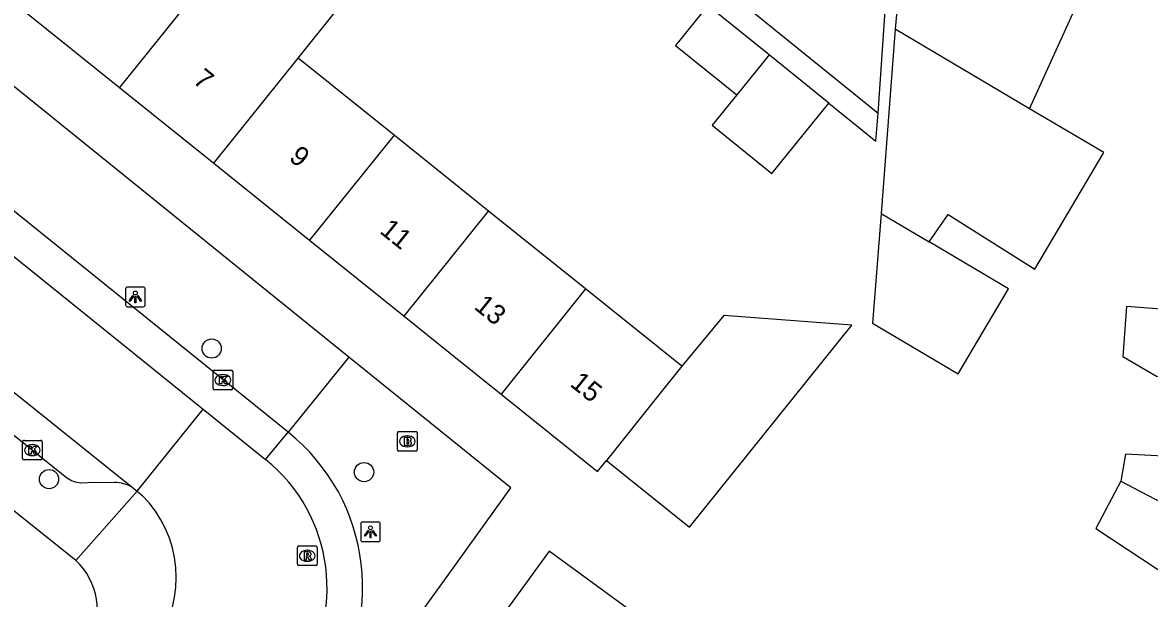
# Model space of a CAD drawing. Extents: x 160107 to 160928, y 382056 to 382918.
# Drawn here: x 160478.2 to 160535.6, y 382552.9 to 382582.2 of the extents above; entities that cross this region are included whole.
import ezdxf

# ---------------------------------------------------------------- set-up
doc = ezdxf.new("R2010")
doc.units = 0
for name, color, linetype in [('IMGEO_Boom', 7, 'Continuous'), ('IMGEO_Brandkraan', 7, 'Continuous'), ('IMGEO_Kolk', 7, 'Continuous'), ('IMGEO_Lichtpunt', 7, 'Continuous'), ('IMGEO_Pand', 7, 'Continuous'), ('IMGEO_Pand_nummerreeks', 7, 'Continuous'), ('IMGEO_Parkeervlak_open', 7, 'Continuous'), ('IMGEO_Rijbaan_lokaal_open', 7, 'Continuous'), ('IMGEO_Rioolput', 7, 'Continuous'), ('IMGEO_Voetpad_open', 7, 'Continuous')]:
    doc.layers.add(name, color=color, linetype=linetype)

msp = doc.modelspace()

# ---------------------------------------------------------------- linework, layer by layer
at = {"layer": 'IMGEO_Boom'}
for centre in [(160487.844, 382565.584), (160479.567, 382558.934), (160495.604, 382559.293)]:
    msp.add_circle(centre, 0.489, dxfattribs=at)
at = {"layer": 'IMGEO_Brandkraan'}
for p, q in [((160497.304, 382560.433), (160497.304, 382561.285)), ((160497.379, 382561.359), (160498.231, 382561.359)), ((160497.792, 382561.139), (160497.817, 382561.139)), ((160498.305, 382561.285), (160498.305, 382560.433)), ((160497.815, 382560.579), (160497.79, 382560.579)), ((160498.231, 382560.359), (160497.379, 382560.359))]:
    msp.add_line(p, q, dxfattribs=at)
for points in [[(160497.304, 382560.433), (160497.304, 382561.285)], [(160497.379, 382561.359), (160498.231, 382561.359)], [(160498.305, 382561.285), (160498.305, 382560.433)], [(160497.652, 382561.059), (160497.652, 382560.659), (160497.865, 382560.659)], [(160497.883, 382561.059), (160497.652, 382561.059)], [(160497.831, 382560.978), (160497.777, 382560.978), (160497.777, 382560.902)], [(160497.777, 382560.902), (160497.83, 382560.902)], [(160497.839, 382560.826), (160497.777, 382560.826), (160497.777, 382560.745)], [(160497.777, 382560.745), (160497.839, 382560.745)], [(160498.231, 382560.359), (160497.379, 382560.359)]]:
    msp.add_lwpolyline(points, dxfattribs=at)
for centre, radius, start, end in [((160497.381, 382561.283), 0.0765, 91.55205, 178.44795), ((160497.381, 382561.283), 0.0765, 91.55205, 178.44795), ((160498.229, 382561.283), 0.0765, 1.55205, 88.44795), ((160498.229, 382561.283), 0.0765, 1.55205, 88.44795), ((160497.832, 382560.94), 0.0379, 267.82845, 90.93552), ((160497.84, 382560.785), 0.0404, 269.87594, 90.50774), ((160497.871, 382560.91), 0.251, 268.66757, 293.53466), ((160497.887, 382560.914), 0.145, 59.4692, 91.53667), ((160497.912, 382560.961), 0.0922, 285.51372, 58.15012), ((160497.917, 382560.769), 0.105, 301.31148, 78.98903), ((160497.381, 382560.435), 0.0765, 181.55205, 268.44795), ((160497.381, 382560.435), 0.0765, 181.55205, 268.44795), ((160498.229, 382560.435), 0.0765, 271.55205, 358.44795), ((160498.229, 382560.435), 0.0765, 271.55205, 358.44795)]:
    msp.add_arc(centre, radius, start, end, dxfattribs=at)
for centre, major_axis, ratio, start_param, end_param in [((160497.791, 382560.859), (-0.387, 0.002), 0.722429, 4.712389, 7.853982), ((160497.816, 382560.859), (-0.39, 0.002), 0.717154, 1.570796, 4.712389)]:
    msp.add_ellipse(centre, major_axis=major_axis, ratio=ratio, start_param=start_param, end_param=end_param, dxfattribs=at)
at = {"layer": 'IMGEO_Kolk'}
for p, q in [((160487.915, 382563.554), (160487.915, 382564.406)), ((160487.99, 382564.48), (160488.842, 382564.48)), ((160488.403, 382564.26), (160488.428, 382564.26)), ((160488.916, 382564.406), (160488.916, 382563.554)), ((160488.842, 382563.48), (160487.99, 382563.48)), ((160488.426, 382563.7), (160488.401, 382563.7)), ((160478.217, 382559.984), (160478.217, 382560.836)), ((160478.292, 382560.91), (160479.144, 382560.91)), ((160478.705, 382560.69), (160478.73, 382560.69)), ((160479.218, 382560.836), (160479.218, 382559.984)), ((160478.728, 382560.13), (160478.703, 382560.13)), ((160479.144, 382559.91), (160478.292, 382559.91))]:
    msp.add_line(p, q, dxfattribs=at)
for points in [[(160487.915, 382563.554), (160487.915, 382564.406)], [(160487.99, 382564.48), (160488.842, 382564.48)], [(160488.236, 382564.18), (160488.359, 382564.18), (160488.359, 382564.029), (160488.489, 382564.18), (160488.653, 382564.18), (160488.507, 382564.029), (160488.66, 382563.78), (160488.508, 382563.78), (160488.423, 382563.944), (160488.359, 382563.877), (160488.359, 382563.78), (160488.236, 382563.78), (160488.236, 382564.18)], [(160488.916, 382564.406), (160488.916, 382563.554)], [(160488.842, 382563.48), (160487.99, 382563.48)], [(160478.217, 382559.984), (160478.217, 382560.836)], [(160478.292, 382560.91), (160479.144, 382560.91)], [(160478.538, 382560.61), (160478.661, 382560.61), (160478.661, 382560.459), (160478.791, 382560.61), (160478.955, 382560.61), (160478.809, 382560.459), (160478.962, 382560.21), (160478.81, 382560.21), (160478.725, 382560.374), (160478.661, 382560.307), (160478.661, 382560.21), (160478.538, 382560.21), (160478.538, 382560.61)], [(160479.218, 382560.836), (160479.218, 382559.984)], [(160479.144, 382559.91), (160478.292, 382559.91)]]:
    msp.add_lwpolyline(points, dxfattribs=at)
for centre, start, end in [((160487.992, 382564.404), 91.55205, 178.44795), ((160487.992, 382564.404), 91.55205, 178.44795), ((160488.84, 382564.404), 1.55205, 88.44795), ((160488.84, 382564.404), 1.55205, 88.44795), ((160487.992, 382563.556), 181.55205, 268.44795), ((160487.992, 382563.556), 181.55205, 268.44795), ((160488.84, 382563.556), 271.55205, 358.44795), ((160488.84, 382563.556), 271.55205, 358.44795), ((160478.294, 382560.834), 91.55205, 178.44795), ((160478.294, 382560.834), 91.55205, 178.44795), ((160479.142, 382560.834), 1.55205, 88.44795), ((160479.142, 382560.834), 1.55205, 88.44795), ((160478.294, 382559.986), 181.55205, 268.44795), ((160478.294, 382559.986), 181.55205, 268.44795), ((160479.142, 382559.986), 271.55205, 358.44795), ((160479.142, 382559.986), 271.55205, 358.44795)]:
    msp.add_arc(centre, 0.0765, start, end, dxfattribs=at)
for centre, major_axis, ratio, start_param, end_param in [((160488.402, 382563.98), (-0.387, 0.002), 0.722429, 4.712389, 7.853982), ((160488.427, 382563.98), (-0.39, 0.002), 0.717154, 1.570796, 4.712389), ((160478.704, 382560.41), (-0.387, 0.002), 0.722429, 4.712389, 7.853982), ((160478.729, 382560.41), (-0.39, 0.002), 0.717154, 1.570796, 4.712389)]:
    msp.add_ellipse(centre, major_axis=major_axis, ratio=ratio, start_param=start_param, end_param=end_param, dxfattribs=at)
at = {"layer": 'IMGEO_Lichtpunt'}
for p, q in [((160483.463, 382568.612), (160483.463, 382567.805)), ((160483.463, 382568.612), (160483.463, 382567.805)), ((160484.365, 382568.707), (160483.557, 382568.707)), ((160484.365, 382568.707), (160483.557, 382568.707)), ((160484.459, 382567.805), (160484.459, 382568.612)), ((160484.459, 382567.805), (160484.459, 382568.612)), ((160483.557, 382567.711), (160484.365, 382567.711)), ((160483.557, 382567.711), (160484.365, 382567.711)), ((160495.431, 382556.655), (160495.431, 382555.848)), ((160495.431, 382556.655), (160495.431, 382555.848)), ((160496.333, 382556.75), (160495.525, 382556.75)), ((160496.333, 382556.75), (160495.525, 382556.75)), ((160496.427, 382555.848), (160496.427, 382556.655)), ((160496.427, 382555.848), (160496.427, 382556.655)), ((160495.525, 382555.754), (160496.333, 382555.754)), ((160495.525, 382555.754), (160496.333, 382555.754))]:
    msp.add_line(p, q, dxfattribs=at)
for points in [[(160483.837, 382568.276), (160483.876, 382568.248), (160483.688, 382567.986), (160483.65, 382568.013), (160483.837, 382568.276)], [(160483.939, 382568.228), (160483.986, 382568.228), (160483.986, 382567.906), (160483.939, 382567.906), (160483.939, 382568.228)], [(160484.049, 382568.248), (160484.087, 382568.275), (160484.274, 382568.013), (160484.235, 382567.985), (160484.049, 382568.248)], [(160495.805, 382556.319), (160495.844, 382556.291), (160495.656, 382556.029), (160495.618, 382556.056), (160495.805, 382556.319)], [(160495.907, 382556.271), (160495.954, 382556.271), (160495.954, 382555.949), (160495.907, 382555.949), (160495.907, 382556.271)], [(160496.017, 382556.291), (160496.055, 382556.318), (160496.242, 382556.056), (160496.203, 382556.028), (160496.017, 382556.291)]]:
    msp.add_lwpolyline(points, dxfattribs=at)
for centre in [(160483.962, 382568.41), (160495.93, 382556.453)]:
    msp.add_circle(centre, 0.0994, dxfattribs=at)
for centre, start, end in [((160483.557, 382568.612), 90, 180), ((160483.557, 382568.612), 90, 180), ((160484.365, 382568.612), 0, 90), ((160484.365, 382568.612), 0, 90), ((160483.557, 382567.805), 180, 270), ((160483.557, 382567.805), 180, 270), ((160484.365, 382567.805), 270, 0), ((160484.365, 382567.805), 270, 360), ((160495.525, 382556.655), 90, 180), ((160495.525, 382556.655), 90, 180), ((160496.333, 382556.655), 0, 90), ((160496.333, 382556.655), 0, 90), ((160495.525, 382555.848), 180, 270), ((160495.525, 382555.848), 180, 270), ((160496.333, 382555.848), 270, 0), ((160496.333, 382555.848), 270, 360)]:
    msp.add_arc(centre, 0.0946, start, end, dxfattribs=at)
at = {"layer": 'IMGEO_Pand'}
for points in [[(160523.021, 382587.864), (160522.708, 382582.592), (160522.649, 382581.836)], [(160492.247, 382580.362), (160494.172, 382582.757), (160489.365, 382586.621), (160487.442, 382584.218)], [(160529.486, 382577.794), (160532.105, 382583.595), (160529.137, 382584.927), (160529.152, 382585.097)], [(160487.442, 382584.218), (160483.149, 382578.878)], [(160513.108, 382583.049), (160511.462, 382581.014), (160514.58, 382578.492)], [(160516.219, 382580.531), (160513.108, 382583.049)], [(160478.25, 382582.816), (160483.149, 382578.878)], [(160522.649, 382581.836), (160521.921, 382572.453)], [(160529.486, 382577.794), (160522.649, 382581.836)], [(160487.952, 382575.018), (160492.247, 382580.362)], [(160497.131, 382576.442), (160492.247, 382580.362)], [(160516.219, 382580.531), (160514.58, 382578.492)], [(160519.258, 382578.07), (160516.219, 382580.531)], [(160483.149, 382578.878), (160487.952, 382575.018)], [(160514.58, 382578.492), (160513.332, 382576.949), (160516.366, 382574.495), (160519.258, 382578.07)], [(160524.366, 382571.009), (160525.337, 382572.407), (160529.753, 382569.63), (160533.26, 382575.563), (160529.486, 382577.794)], [(160497.131, 382576.442), (160492.833, 382571.095)], [(160501.942, 382572.581), (160500, 382574.14), (160497.131, 382576.442)], [(160487.952, 382575.018), (160492.833, 382571.095)], [(160497.641, 382567.23), (160500, 382570.165), (160501.942, 382572.581)], [(160506.884, 382568.616), (160501.942, 382572.581)], [(160521.921, 382572.453), (160521.488, 382566.867), (160525.848, 382564.292), (160528.406, 382568.623), (160524.366, 382571.009)], [(160521.921, 382572.453), (160524.366, 382571.009)], [(160492.833, 382571.095), (160497.641, 382567.23)], [(160552.564, 382569.329), (160547.58, 382569.718), (160544.296, 382569.974), (160541.327, 382570.206), (160541.092, 382567.202), (160538.823, 382567.379), (160534.423, 382567.722), (160534.226, 382565.184), (160535.938, 382564.173), (160538.538, 382563.615), (160543.727, 382563.248), (160547.056, 382562.989), (160552.04, 382562.601)], [(160506.884, 382568.616), (160502.579, 382563.261)], [(160511.788, 382564.68), (160506.884, 382568.616)], [(160497.641, 382567.23), (160500, 382565.334), (160502.579, 382563.261)], [(160507.938, 382559.891), (160512.167, 382556.49), (160520.438, 382566.776), (160513.923, 382567.267), (160511.788, 382564.68)], [(160511.788, 382564.68), (160510.614, 382563.219), (160507.938, 382559.891)], [(160502.579, 382563.261), (160507.48, 382559.322), (160507.938, 382559.891)], [(160551.827, 382561.414), (160546.852, 382561.905), (160543.549, 382562.231), (160543.303, 382559.732), (160538.255, 382559.998), (160534.372, 382560.203), (160534.13, 382558.833)], [(160534.13, 382558.833), (160532.862, 382556.422), (160537.595, 382553.305), (160539.806, 382553.087), (160539.529, 382550.277), (160539.612, 382549.61), (160539.842, 382548.94), (160540.177, 382548.324), (160540.742, 382547.567), (160541.272, 382547.092), (160542.048, 382546.688), (160542.701, 382546.424), (160550.275, 382545.677), (160550.406, 382547)], [(160534.13, 382558.833), (160537.943, 382556.836), (160538.099, 382556.743), (160538.999, 382556.655), (160551.24, 382555.455)], [(160509.011, 382545.449), (160512.289, 382549.95), (160509.068, 382552.309), (160505.035, 382555.264), (160501.74, 382550.735)]]:
    msp.add_lwpolyline(points, dxfattribs=at)
at = {"layer": 'IMGEO_Parkeervlak_open'}
msp.add_lwpolyline([(160490.592, 382559.937), (160491.735, 382561.326)], dxfattribs=at)
at = {"layer": 'IMGEO_Rijbaan_lokaal_open'}
for points in [[(160521.777, 382577.568), (160522.529, 382588.511), (160523.188, 382598.313), (160523.787, 382607.377), (160524.568, 382619.515), (160524.9, 382624.057), (160525.288, 382624.05)], [(160482.098, 382608.167), (160482.828, 382609.057), (160500, 382595.174), (160521.777, 382577.568)], [(160437.847, 382595.414), (160450.577, 382585.198), (160483.799, 382558.523)], [(160463.099, 382582.104), (160487.415, 382562.498)], [(160484.046, 382558.32), (160487.415, 382562.498)], [(160487.415, 382562.498), (160490.592, 382559.937)], [(160483.799, 382558.523), (160484.046, 382558.32)], [(160484.046, 382558.32), (160484.294, 382558.117)]]:
    msp.add_lwpolyline(points, dxfattribs=at)
for centre, radius, start, end in [((160485.315, 382553.397), 8.404, 323.46052, 51.10216), ((160480.17, 382553.936), 5.873, 324.497, 45.39493)]:
    msp.add_arc(centre, radius, start, end, dxfattribs=at)
at = {"layer": 'IMGEO_Rioolput'}
for p, q in [((160492.212, 382554.605), (160492.212, 382555.457)), ((160492.287, 382555.531), (160493.139, 382555.531)), ((160493.213, 382555.457), (160493.213, 382554.605)), ((160492.7, 382555.311), (160492.725, 382555.311)), ((160493.139, 382554.531), (160492.287, 382554.531)), ((160492.723, 382554.751), (160492.698, 382554.751))]:
    msp.add_line(p, q, dxfattribs=at)
for points in [[(160492.212, 382554.605), (160492.212, 382555.457)], [(160492.287, 382555.531), (160493.139, 382555.531)], [(160493.213, 382555.457), (160493.213, 382554.605)], [(160492.801, 382555.229), (160492.549, 382555.231), (160492.549, 382554.831)], [(160492.549, 382554.831), (160492.673, 382554.831), (160492.673, 382554.993), (160492.684, 382554.993)], [(160492.727, 382555.15), (160492.673, 382555.15), (160492.673, 382555.069)], [(160492.673, 382555.069), (160492.725, 382555.069)], [(160492.731, 382554.964), (160492.802, 382554.831), (160492.942, 382554.831), (160492.877, 382554.957)], [(160493.139, 382554.531), (160492.287, 382554.531)]]:
    msp.add_lwpolyline(points, dxfattribs=at)
for centre, radius, start, end in [((160492.289, 382555.455), 0.0765, 91.55205, 178.44795), ((160492.289, 382555.455), 0.0765, 91.55205, 178.44795), ((160493.137, 382555.455), 0.0765, 1.55205, 88.44795), ((160493.137, 382555.455), 0.0765, 1.55205, 88.44795), ((160492.683, 382554.94), 0.0533, 26.02933, 88.69889), ((160492.709, 382555.258), 0.19, 274.7715, 282.96867), ((160492.733, 382555.054), 0.0964, 77.00612, 93.18647), ((160492.747, 382555.111), 0.0378, 276.66336, 79.67722), ((160492.8, 382555.119), 0.109, 350.36119, 89.41601), ((160492.798, 382555.119), 0.112, 277.58423, 350.98172), ((160492.782, 382554.904), 0.108, 29.51342, 73.79051), ((160492.289, 382554.607), 0.0765, 181.55205, 268.44795), ((160492.289, 382554.607), 0.0765, 181.55205, 268.44795), ((160493.137, 382554.607), 0.0765, 271.55205, 358.44795), ((160493.137, 382554.607), 0.0765, 271.55205, 358.44795)]:
    msp.add_arc(centre, radius, start, end, dxfattribs=at)
for centre, major_axis, ratio, start_param, end_param in [((160492.699, 382555.031), (-0.387, 0.002), 0.722429, 4.712389, 7.853982), ((160492.724, 382555.031), (-0.39, 0.002), 0.717154, 1.570796, 4.712389)]:
    msp.add_ellipse(centre, major_axis=major_axis, ratio=ratio, start_param=start_param, end_param=end_param, dxfattribs=at)
at = {"layer": 'IMGEO_Voetpad_open'}
for points in [[(160438.907, 382592.26), (160448.753, 382584.442), (160458.029, 382576.973), (160473.398, 382564.68), (160480.457, 382559.016)], [(160494.827, 382565.152), (160466.307, 382588.202)], [(160491.735, 382561.326), (160466.43, 382581.731)], [(160519.258, 382578.07), (160521.653, 382576.138), (160521.777, 382577.568)], [(160494.827, 382565.152), (160491.735, 382561.326)], [(160491.895, 382542.979), (160500, 382554.224), (160503.073, 382558.488), (160500, 382560.972), (160494.827, 382565.152)], [(160480.93, 382554.797), (160474.597, 382559.852)], [(160480.93, 382554.797), (160484.046, 382558.32)], [(160481.177, 382558.75), (160481.883, 382558.782), (160482.896, 382558.763)]]:
    msp.add_lwpolyline(points, dxfattribs=at)
for centre, radius, start, end in [((160485.409, 382553.42), 10.125, 322.25978, 51.33476), ((160481.299, 382560.189), 1.444, 234.31212, 265.13494), ((160482.881, 382556.886), 1.877, 60.70366, 89.52831), ((160478.52, 382552.242), 3.512, 332.28259, 46.66868)]:
    msp.add_arc(centre, radius, start, end, dxfattribs=at)

# ---------------------------------------------------------------- texts
at = {"layer": 'IMGEO_Pand_nummerreeks'}
for s, rotation, p in [('7', 321.21076, (160486.842, 382579.143)), ('9', 321.20914, (160491.731, 382575.214)), ('11', 321.20914, (160496.35, 382571.5)), ('13', 321.20914, (160501.151, 382567.642)), ('15', 321.21076, (160506.04, 382563.712))]:
    msp.add_text(s, height=1, rotation=rotation, dxfattribs=at).set_placement(p)

doc.saveas('drawing.dxf')
